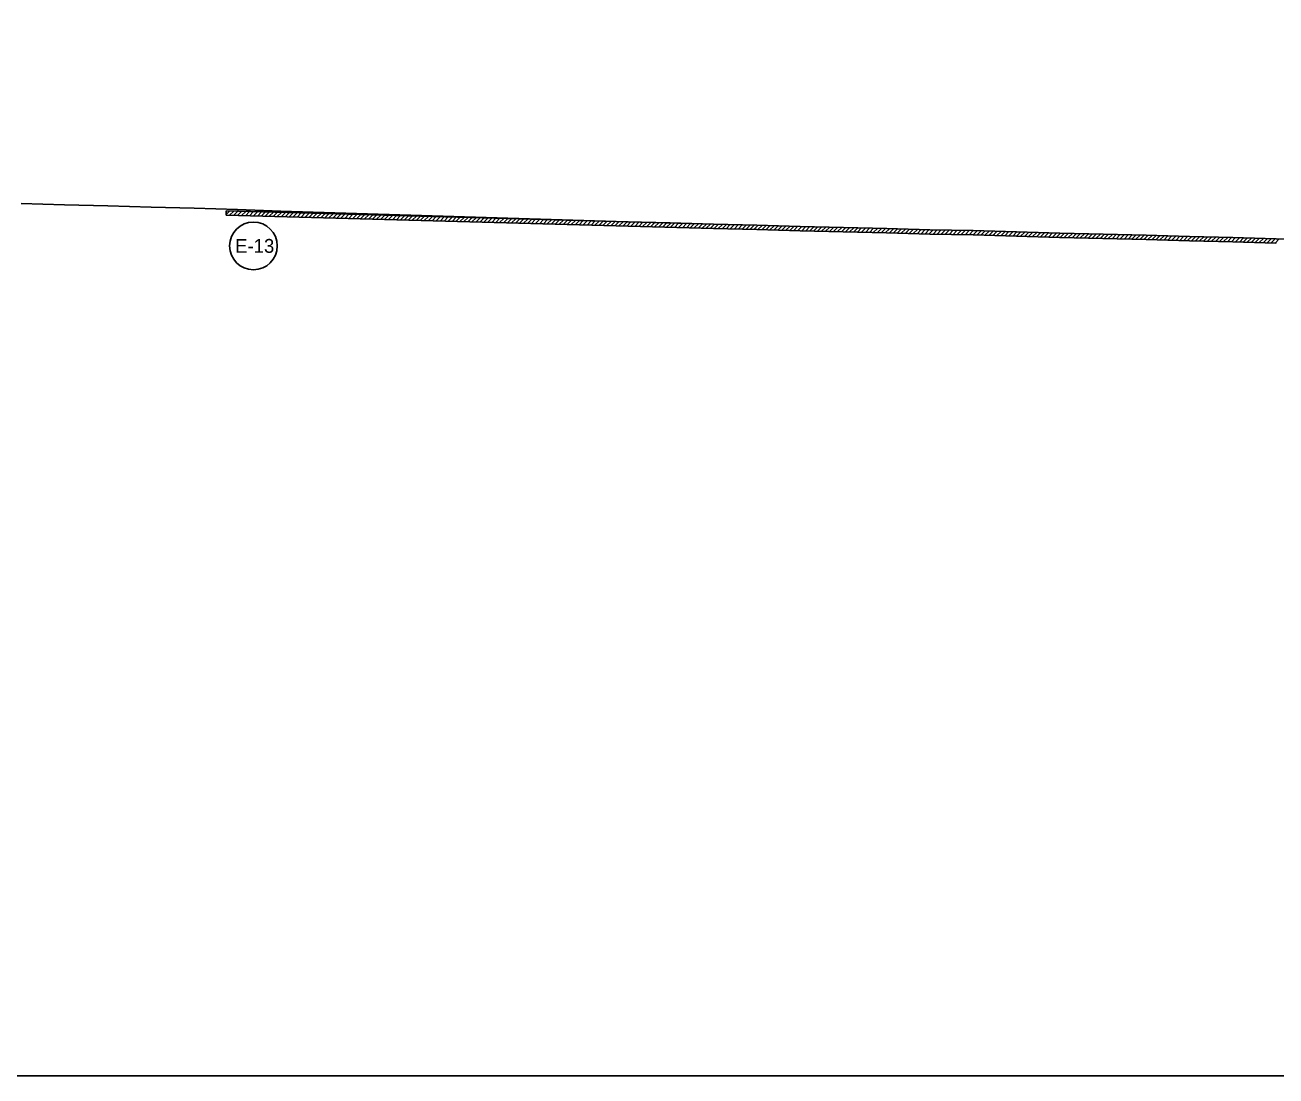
# Model space of a CAD drawing. Extents: x 976877 to 983987, y 1525984 to 1526526.
# Drawn here: x 982149.7 to 982583.2, y 1526043.8 to 1526408 of the extents above; entities that cross this region are included whole.
import ezdxf

# ---------------------------------------------------------------- set-up
doc = ezdxf.new("R2010")
doc.units = 0
doc.layers.add('R_Erosion', color=7, linetype='Continuous')
doc.layers.add('R_No Plot', color=7, linetype='Continuous')

msp = doc.modelspace()

# ---------------------------------------------------------------- linework, layer by layer
at = {"layer": 'R_Erosion'}
for p, q in [((982219.38, 1526343.59), (982219.34, 1526342.09)), ((982219.38, 1526343.59), (982219.34, 1526342.09)), ((982219.34, 1526342.09), (982388.23, 1526337.46)), ((982219.34, 1526342.09), (982388.23, 1526337.46)), ((982219.34, 1526342.09), (982388.23, 1526337.46)), ((982219.35, 1526342.28), (982220.62, 1526343.55)), ((982220.53, 1526342.05), (982221.99, 1526343.51)), ((982221.91, 1526342.02), (982223.37, 1526343.48)), ((982223.29, 1526341.98), (982224.75, 1526343.44)), ((982224.66, 1526341.94), (982226.12, 1526343.4)), ((982226.04, 1526341.9), (982227.5, 1526343.36)), ((982227.42, 1526341.87), (982228.88, 1526343.33)), ((982228.79, 1526341.83), (982230.25, 1526343.29)), ((982230.17, 1526341.79), (982231.63, 1526343.25)), ((982231.54, 1526341.75), (982233.01, 1526343.21)), ((982232.92, 1526341.71), (982234.38, 1526343.18)), ((982234.3, 1526341.68), (982235.76, 1526343.14)), ((982235.67, 1526341.64), (982237.13, 1526343.1)), ((982237.05, 1526341.6), (982238.51, 1526343.06)), ((982238.43, 1526341.56), (982239.89, 1526343.02)), ((982239.8, 1526341.53), (982241.26, 1526342.99)), ((982241.18, 1526341.49), (982242.64, 1526342.95)), ((982242.56, 1526341.45), (982244.02, 1526342.91)), ((982243.93, 1526341.41), (982245.39, 1526342.87)), ((982245.31, 1526341.37), (982246.77, 1526342.84)), ((982246.69, 1526341.34), (982248.15, 1526342.8)), ((982248.06, 1526341.3), (982249.52, 1526342.76)), ((982249.44, 1526341.26), (982250.9, 1526342.72)), ((982250.82, 1526341.22), (982252.28, 1526342.68)), ((982252.19, 1526341.19), (982253.65, 1526342.65)), ((982253.57, 1526341.15), (982255.03, 1526342.61)), ((982254.95, 1526341.11), (982256.41, 1526342.57)), ((982256.32, 1526341.07), (982257.78, 1526342.53)), ((982257.7, 1526341.04), (982259.16, 1526342.5)), ((982259.07, 1526341), (982260.54, 1526342.46)), ((982260.45, 1526340.96), (982261.91, 1526342.42)), ((982261.83, 1526340.92), (982263.29, 1526342.38)), ((982263.2, 1526340.88), (982264.66, 1526342.35)), ((982264.58, 1526340.85), (982266.04, 1526342.31)), ((982265.96, 1526340.81), (982267.42, 1526342.27)), ((982267.33, 1526340.77), (982268.79, 1526342.23)), ((982268.71, 1526340.73), (982270.17, 1526342.19)), ((982270.09, 1526340.7), (982271.55, 1526342.16)), ((982271.46, 1526340.66), (982272.92, 1526342.12)), ((982272.84, 1526340.62), (982274.3, 1526342.08)), ((982274.22, 1526340.58), (982275.68, 1526342.04)), ((982275.59, 1526340.54), (982277.05, 1526342.01)), ((982276.97, 1526340.51), (982278.43, 1526341.97)), ((982278.35, 1526340.47), (982279.81, 1526341.93)), ((982279.72, 1526340.43), (982281.18, 1526341.89)), ((982281.1, 1526340.39), (982282.56, 1526341.85)), ((982282.47, 1526340.36), (982283.94, 1526341.82)), ((982283.85, 1526340.32), (982285.31, 1526341.78)), ((982285.23, 1526340.28), (982286.69, 1526341.74)), ((982286.6, 1526340.24), (982288.06, 1526341.7)), ((982287.98, 1526340.21), (982289.44, 1526341.67)), ((982289.36, 1526340.17), (982290.82, 1526341.63)), ((982290.73, 1526340.13), (982292.19, 1526341.59)), ((982292.11, 1526340.09), (982293.57, 1526341.55)), ((982293.49, 1526340.05), (982294.95, 1526341.52)), ((982294.86, 1526340.02), (982296.32, 1526341.48)), ((982296.24, 1526339.98), (982297.7, 1526341.44)), ((982297.62, 1526339.94), (982299.08, 1526341.4)), ((982298.99, 1526339.9), (982300.45, 1526341.36)), ((982300.37, 1526339.87), (982301.83, 1526341.33)), ((982301.75, 1526339.83), (982303.21, 1526341.29)), ((982303.12, 1526339.79), (982304.58, 1526341.25)), ((982304.5, 1526339.75), (982305.96, 1526341.21)), ((982305.88, 1526339.71), (982307.34, 1526341.18)), ((982307.25, 1526339.68), (982308.71, 1526341.14)), ((982308.63, 1526339.64), (982310.09, 1526341.1)), ((982310, 1526339.6), (982311.47, 1526341.06)), ((982311.38, 1526339.56), (982312.84, 1526341.02)), ((982312.76, 1526339.53), (982314.22, 1526340.99)), ((982314.13, 1526339.49), (982315.59, 1526340.95)), ((982315.51, 1526339.45), (982316.97, 1526340.91)), ((982316.89, 1526339.41), (982318.35, 1526340.87)), ((982318.26, 1526339.38), (982319.72, 1526340.84)), ((982319.64, 1526339.34), (982321.1, 1526340.8)), ((982321.02, 1526339.3), (982322.48, 1526340.76)), ((982322.39, 1526339.26), (982323.85, 1526340.72)), ((982323.77, 1526339.22), (982325.23, 1526340.69)), ((982325.15, 1526339.19), (982326.61, 1526340.65)), ((982326.52, 1526339.15), (982327.98, 1526340.61)), ((982327.9, 1526339.11), (982329.36, 1526340.57)), ((982329.28, 1526339.07), (982330.74, 1526340.53)), ((982330.65, 1526339.04), (982332.11, 1526340.5)), ((982332.03, 1526339), (982333.49, 1526340.46)), ((982333.4, 1526338.96), (982334.87, 1526340.42)), ((982334.78, 1526338.92), (982336.24, 1526340.38)), ((982336.16, 1526338.88), (982337.62, 1526340.35)), ((982337.53, 1526338.85), (982338.99, 1526340.31)), ((982338.91, 1526338.81), (982340.37, 1526340.27)), ((982340.29, 1526338.77), (982341.75, 1526340.23)), ((982341.66, 1526338.73), (982343.12, 1526340.19)), ((982343.04, 1526338.7), (982344.5, 1526340.16)), ((982344.42, 1526338.66), (982345.88, 1526340.12)), ((982345.79, 1526338.62), (982347.25, 1526340.08)), ((982347.17, 1526338.58), (982348.63, 1526340.04)), ((982348.55, 1526338.55), (982350.01, 1526340.01)), ((982349.92, 1526338.51), (982351.38, 1526339.97)), ((982351.3, 1526338.47), (982352.76, 1526339.93)), ((982352.68, 1526338.43), (982354.14, 1526339.89)), ((982354.05, 1526338.39), (982355.51, 1526339.85)), ((982355.43, 1526338.36), (982356.89, 1526339.82)), ((982356.81, 1526338.32), (982358.27, 1526339.78)), ((982358.18, 1526338.28), (982359.64, 1526339.74)), ((982359.56, 1526338.24), (982361.02, 1526339.7)), ((982360.93, 1526338.21), (982362.4, 1526339.67)), ((982362.31, 1526338.17), (982363.77, 1526339.63)), ((982363.69, 1526338.13), (982365.15, 1526339.59)), ((982365.06, 1526338.09), (982366.52, 1526339.55)), ((982366.44, 1526338.05), (982367.9, 1526339.52)), ((982367.82, 1526338.02), (982369.28, 1526339.48)), ((982369.19, 1526337.98), (982370.65, 1526339.44)), ((982370.57, 1526337.94), (982372.03, 1526339.4)), ((982371.95, 1526337.9), (982373.41, 1526339.36)), ((982373.32, 1526337.87), (982374.78, 1526339.33)), ((982374.7, 1526337.83), (982376.16, 1526339.29)), ((982376.08, 1526337.79), (982377.54, 1526339.25)), ((982377.45, 1526337.75), (982378.91, 1526339.21)), ((982378.83, 1526337.72), (982380.29, 1526339.18)), ((982380.21, 1526337.68), (982381.67, 1526339.14)), ((982381.58, 1526337.64), (982383.04, 1526339.1)), ((982382.96, 1526337.6), (982384.42, 1526339.06)), ((982384.33, 1526337.56), (982385.8, 1526339.02)), ((982385.71, 1526337.53), (982387.17, 1526338.99)), ((982387.09, 1526337.49), (982388.55, 1526338.95)), ((982388.24, 1526337.46), (982403.23, 1526337.08)), ((982388.24, 1526337.46), (982403.23, 1526337.08)), ((982388.24, 1526337.46), (982403.23, 1526337.08)), ((982388.46, 1526337.45), (982389.93, 1526338.92)), ((982389.84, 1526337.42), (982391.31, 1526338.88)), ((982391.22, 1526337.38), (982392.69, 1526338.85)), ((982392.6, 1526337.35), (982394.07, 1526338.81)), ((982393.98, 1526337.31), (982395.45, 1526338.78)), ((982395.36, 1526337.28), (982396.82, 1526338.74)), ((982396.74, 1526337.24), (982398.2, 1526338.71)), ((982398.12, 1526337.21), (982399.58, 1526338.67)), ((982399.5, 1526337.17), (982400.96, 1526338.64)), ((982400.88, 1526337.14), (982402.34, 1526338.6)), ((982402.26, 1526337.1), (982403.72, 1526338.57)), ((982403.64, 1526337.07), (982405.1, 1526338.53)), ((982405.02, 1526337.03), (982406.48, 1526338.5)), ((982406.4, 1526337), (982407.86, 1526338.46)), ((982407.78, 1526336.97), (982409.24, 1526338.43)), ((982409.16, 1526336.93), (982410.62, 1526338.4)), ((982410.54, 1526336.9), (982412, 1526338.36)), ((982411.92, 1526336.86), (982413.38, 1526338.33)), ((982413.3, 1526336.83), (982414.76, 1526338.29)), ((982414.68, 1526336.8), (982416.14, 1526338.26)), ((982416.06, 1526336.76), (982417.52, 1526338.23)), ((982417.44, 1526336.73), (982418.9, 1526338.19)), ((982433.26, 1526337.82), (982418.27, 1526338.21)), ((982433.26, 1526337.82), (982418.27, 1526338.21)), ((982418.82, 1526336.69), (982420.28, 1526338.16)), ((982420.2, 1526336.66), (982421.66, 1526338.12)), ((982421.58, 1526336.62), (982423.04, 1526338.08)), ((982422.95, 1526336.59), (982424.42, 1526338.05)), ((982424.33, 1526336.55), (982425.8, 1526338.01)), ((982425.71, 1526336.52), (982427.18, 1526337.98)), ((982427.09, 1526336.48), (982428.55, 1526337.94)), ((982428.47, 1526336.44), (982429.93, 1526337.91)), ((982429.85, 1526336.41), (982431.31, 1526337.87)), ((982431.23, 1526336.37), (982432.69, 1526337.84)), ((982432.61, 1526336.34), (982434.07, 1526337.8)), ((982433.98, 1526336.3), (982435.45, 1526337.76)), ((982435.36, 1526336.26), (982436.82, 1526337.73)), ((982436.74, 1526336.23), (982438.2, 1526337.69)), ((982438.12, 1526336.19), (982439.58, 1526337.65)), ((982439.49, 1526336.15), (982440.95, 1526337.61)), ((982440.87, 1526336.12), (982442.33, 1526337.58)), ((982442.25, 1526336.08), (982443.71, 1526337.54)), ((982443.62, 1526336.04), (982445.08, 1526337.5)), ((982445, 1526336), (982446.46, 1526337.47)), ((982446.38, 1526335.97), (982447.84, 1526337.43)), ((982447.75, 1526335.93), (982449.22, 1526337.39)), ((982448.22, 1526335.92), (982463.21, 1526335.55)), ((982448.22, 1526335.92), (982463.21, 1526335.55)), ((982448.22, 1526335.92), (982463.21, 1526335.55)), ((982449.13, 1526335.9), (982450.6, 1526337.36)), ((982450.51, 1526335.86), (982451.98, 1526337.33)), ((982451.89, 1526335.83), (982453.36, 1526337.29)), ((982453.28, 1526335.79), (982454.74, 1526337.26)), ((982454.66, 1526335.76), (982456.12, 1526337.23)), ((982456.04, 1526335.73), (982457.5, 1526337.19)), ((982457.42, 1526335.69), (982458.88, 1526337.16)), ((982458.8, 1526335.66), (982460.26, 1526337.12)), ((982460.18, 1526335.63), (982461.64, 1526337.09)), ((982461.56, 1526335.59), (982463.02, 1526337.06)), ((982462.94, 1526335.56), (982464.41, 1526337.03)), ((982464.32, 1526335.53), (982465.79, 1526337)), ((982465.71, 1526335.5), (982467.18, 1526336.97)), ((982467.09, 1526335.47), (982468.56, 1526336.94)), ((982468.48, 1526335.44), (982469.95, 1526336.91)), ((982469.86, 1526335.41), (982471.33, 1526336.88)), ((982471.25, 1526335.38), (982472.72, 1526336.85)), ((982472.64, 1526335.36), (982474.1, 1526336.82)), ((982474.02, 1526335.33), (982475.49, 1526336.8)), ((982475.41, 1526335.3), (982476.88, 1526336.77)), ((982476.79, 1526335.27), (982478.26, 1526336.74)), ((982478.18, 1526335.24), (982479.63, 1526336.7)), ((982493.24, 1526336.3), (982478.25, 1526336.74)), ((982493.24, 1526336.3), (982478.25, 1526336.74)), ((982479.55, 1526335.2), (982481.01, 1526336.66)), ((982480.93, 1526335.16), (982482.38, 1526336.62)), ((982482.3, 1526335.12), (982483.76, 1526336.58)), ((982483.67, 1526335.08), (982485.13, 1526336.54)), ((982485.05, 1526335.04), (982486.51, 1526336.5)), ((982486.42, 1526335), (982487.88, 1526336.46)), ((982487.8, 1526334.96), (982489.26, 1526336.42)), ((982489.17, 1526334.92), (982490.63, 1526336.38)), ((982490.55, 1526334.88), (982492, 1526336.34)), ((982491.92, 1526334.84), (982493.38, 1526336.3)), ((982493.29, 1526334.8), (982494.75, 1526336.26)), ((982494.67, 1526334.76), (982496.13, 1526336.22)), ((982496.04, 1526334.72), (982497.5, 1526336.18)), ((982497.42, 1526334.68), (982498.87, 1526336.14)), ((982498.79, 1526334.64), (982500.25, 1526336.1)), ((982500.16, 1526334.6), (982501.62, 1526336.06)), ((982501.54, 1526334.56), (982502.99, 1526336.01)), ((982502.91, 1526334.52), (982504.37, 1526335.97)), ((982504.28, 1526334.48), (982505.74, 1526335.93)), ((982505.66, 1526334.43), (982507.11, 1526335.89)), ((982507.03, 1526334.39), (982508.49, 1526335.85)), ((982508.4, 1526334.35), (982509.87, 1526335.82)), ((982509.79, 1526334.32), (982511.25, 1526335.79)), ((982511.17, 1526334.29), (982512.64, 1526335.76)), ((982512.55, 1526334.26), (982514.02, 1526335.73)), ((982513.93, 1526334.23), (982515.4, 1526335.69)), ((982515.32, 1526334.2), (982516.78, 1526335.66)), ((982516.7, 1526334.16), (982518.16, 1526335.63)), ((982518.08, 1526334.13), (982519.55, 1526335.6)), ((982519.46, 1526334.1), (982520.93, 1526335.57)), ((982520.85, 1526334.07), (982522.31, 1526335.53)), ((982522.23, 1526334.04), (982523.69, 1526335.5)), ((982538.22, 1526335.12), (982523.23, 1526335.51)), ((982538.22, 1526335.12), (982523.23, 1526335.51)), ((982523.61, 1526334), (982525.07, 1526335.46)), ((982524.99, 1526333.97), (982526.45, 1526335.43)), ((982526.36, 1526333.93), (982527.83, 1526335.39)), ((982527.74, 1526333.89), (982529.21, 1526335.36)), ((982529.12, 1526333.86), (982530.58, 1526335.32)), ((982530.5, 1526333.82), (982531.96, 1526335.29)), ((982531.88, 1526333.79), (982533.34, 1526335.25)), ((982533.26, 1526333.75), (982534.72, 1526335.21)), ((982534.63, 1526333.71), (982536.1, 1526335.18)), ((982536.01, 1526333.68), (982537.48, 1526335.14)), ((982537.39, 1526333.64), (982538.85, 1526335.11)), ((982538.77, 1526333.61), (982540.23, 1526335.07)), ((982540.15, 1526333.57), (982541.61, 1526335.03)), ((982541.53, 1526333.54), (982542.99, 1526335)), ((982542.9, 1526333.5), (982544.37, 1526334.96)), ((982544.28, 1526333.46), (982545.74, 1526334.93)), ((982545.66, 1526333.43), (982547.12, 1526334.89)), ((982547.04, 1526333.39), (982548.5, 1526334.85)), ((982548.42, 1526333.35), (982549.88, 1526334.82)), ((982549.79, 1526333.32), (982551.26, 1526334.78)), ((982551.17, 1526333.28), (982552.64, 1526334.75)), ((982552.55, 1526333.25), (982554.01, 1526334.71)), ((982553.93, 1526333.21), (982555.39, 1526334.67)), ((982555.31, 1526333.17), (982556.77, 1526334.64)), ((982556.69, 1526333.14), (982558.15, 1526334.6)), ((982558.06, 1526333.1), (982559.53, 1526334.57)), ((982559.44, 1526333.07), (982560.9, 1526334.53)), ((982560.82, 1526333.03), (982562.28, 1526334.49)), ((982562.2, 1526333), (982563.66, 1526334.46)), ((982563.58, 1526332.96), (982565.04, 1526334.42)), ((982564.96, 1526332.92), (982566.42, 1526334.39)), ((982566.33, 1526332.89), (982567.8, 1526334.35)), ((982567.71, 1526332.85), (982569.17, 1526334.31)), ((982569.09, 1526332.81), (982570.55, 1526334.27)), ((982570.46, 1526332.78), (982571.93, 1526334.24)), ((982571.84, 1526332.74), (982573.3, 1526334.2)), ((982573.22, 1526332.7), (982574.68, 1526334.16)), ((982574.59, 1526332.66), (982576.05, 1526334.12)), ((982575.97, 1526332.62), (982577.43, 1526334.08)), ((982577.35, 1526332.58), (982578.81, 1526334.04)), ((982578.72, 1526332.55), (982580.18, 1526334.01)), ((982580.1, 1526332.51), (982581.56, 1526333.97)), ((982581.47, 1526332.47), (982582.93, 1526333.93)), ((982582.85, 1526332.43), (982584.31, 1526333.89))]:
    msp.add_line(p, q, dxfattribs=at)
for points in [[(982418.26, 1526338.21), (982403.27, 1526338.58), (982388.27, 1526338.96), (982219.38, 1526343.59)], [(982418.26, 1526338.21), (982403.27, 1526338.58), (982388.27, 1526338.96), (982219.38, 1526343.59)], [(982403.23, 1526337.08), (982418.23, 1526336.71), (982433.22, 1526336.32), (982448.21, 1526335.92)], [(982403.23, 1526337.08), (982418.23, 1526336.71), (982433.22, 1526336.32), (982448.21, 1526335.92)], [(982403.23, 1526337.08), (982418.23, 1526336.71), (982433.22, 1526336.32), (982448.21, 1526335.92)], [(982478.24, 1526336.74), (982463.25, 1526337.05), (982448.25, 1526337.42), (982433.26, 1526337.82)], [(982478.24, 1526336.74), (982463.25, 1526337.05), (982448.25, 1526337.42), (982433.26, 1526337.82)], [(982463.22, 1526335.55), (982478.21, 1526335.24), (982493.2, 1526334.8), (982508.19, 1526334.36)], [(982463.22, 1526335.55), (982478.21, 1526335.24), (982493.2, 1526334.8), (982508.19, 1526334.36)], [(982463.22, 1526335.55), (982478.21, 1526335.24), (982493.2, 1526334.8), (982508.19, 1526334.36)], [(982523.22, 1526335.51), (982508.23, 1526335.86), (982493.24, 1526336.3)], [(982523.22, 1526335.51), (982508.23, 1526335.86), (982493.24, 1526336.3)], [(982508.2, 1526334.36), (982523.19, 1526334.01), (982538.18, 1526333.62), (982553.17, 1526333.23)], [(982508.2, 1526334.36), (982523.19, 1526334.01), (982538.18, 1526333.62), (982553.17, 1526333.23)], [(982508.2, 1526334.36), (982523.19, 1526334.01), (982538.18, 1526333.62), (982553.17, 1526333.23)], [(982568.21, 1526334.34), (982553.21, 1526334.73), (982538.22, 1526335.12)], [(982568.21, 1526334.34), (982553.21, 1526334.73), (982538.22, 1526335.12)], [(982553.17, 1526333.23), (982568.17, 1526332.84), (982583.16, 1526332.42)], [(982553.17, 1526333.23), (982568.17, 1526332.84), (982583.16, 1526332.42)], [(982553.17, 1526333.23), (982568.17, 1526332.84), (982583.16, 1526332.42)], [(982598.19, 1526333.51), (982583.2, 1526333.92), (982568.21, 1526334.34)], [(982598.19, 1526333.51), (982583.2, 1526333.92), (982568.21, 1526334.34)]]:
    msp.add_lwpolyline(points, dxfattribs=at)
msp.add_circle((982228.81, 1526331.43), 8.26, dxfattribs=at)
for centre, start, end in [((982388.27, 1526338.96), 268.43, 268.5522), ((982388.27, 1526338.96), 268.43, 268.5522), ((982388.27, 1526338.96), 268.43, 268.5522), ((982403.27, 1526338.58), 268.5522, 268.5827), ((982403.27, 1526338.58), 268.5522, 268.5827), ((982418.23, 1526336.71), 88.5292, 88.5827), ((982433.22, 1526336.32), 88.4529, 88.5292), ((982433.22, 1526336.32), 88.4529, 88.5292), ((982448.25, 1526337.42), 268.4529, 268.6056), ((982448.25, 1526337.42), 268.4529, 268.6056), ((982448.25, 1526337.42), 268.4529, 268.6056), ((982463.25, 1526337.05), 268.6056, 268.8005), ((982463.25, 1526337.05), 268.6056, 268.8005), ((982463.25, 1526337.05), 268.6056, 268.8005), ((982478.21, 1526335.24), 88.3419, 88.8005), ((982478.21, 1526335.24), 88.3419, 88.8005), ((982493.2, 1526334.8), 88.3, 88.3419), ((982508.23, 1526335.86), 268.3, 268.6776), ((982508.23, 1526335.86), 268.3, 268.6776), ((982508.23, 1526335.86), 268.3, 268.6776), ((982523.19, 1526334.01), 88.5063, 88.6776), ((982523.19, 1526334.01), 88.5063, 88.6776), ((982538.18, 1526333.62), 88.5024, 88.5063), ((982553.21, 1526334.73), 268.5024, 268.5063), ((982568.17, 1526332.84), 88.4108, 88.5063), ((982583.2, 1526333.92), 268.4108, 268.4146)]:
    msp.add_arc(centre, 1.5, start, end, dxfattribs=at)
at = {"layer": 'R_No Plot'}
for points in [[(980311.86, 1526407.98), (980311.86, 1526043.76), (983987.45, 1526043.76), (983987.45, 1526292.17)], [(982583.2, 1526333.92), (982568.21, 1526334.34), (982553.21, 1526334.73), (982538.22, 1526335.12), (982523.22, 1526335.51), (982508.23, 1526335.86), (982493.24, 1526336.3), (982478.25, 1526336.74), (982463.25, 1526337.05), (982448.25, 1526337.42), (982433.26, 1526337.82), (982418.26, 1526338.21), (982403.27, 1526338.58), (982388.27, 1526338.96), (982373.28, 1526339.37), (982358.27, 1526339.78), (982343.27, 1526340.18), (982328.28, 1526340.72), (982313.29, 1526341.19), (982298.29, 1526341.59), (982283.3, 1526342.08), (982268.31, 1526342.51), (982253.31, 1526342.95), (982238.32, 1526343.49), (982223.31, 1526344), (982208.31, 1526344.48), (982193.32, 1526344.87), (982178.32, 1526345.27), (982163.33, 1526345.71), (982148.34, 1526346.17)]]:
    msp.add_lwpolyline(points, dxfattribs=at)
msp.add_circle((982228.81, 1526331.43), 8.26, dxfattribs=at)

# ---------------------------------------------------------------- texts
at = {"layer": 'R_Erosion'}
msp.add_text('E-13', height=4.8, dxfattribs=at).set_placement((982222.48, 1526329.03))

doc.saveas('drawing.dxf')
